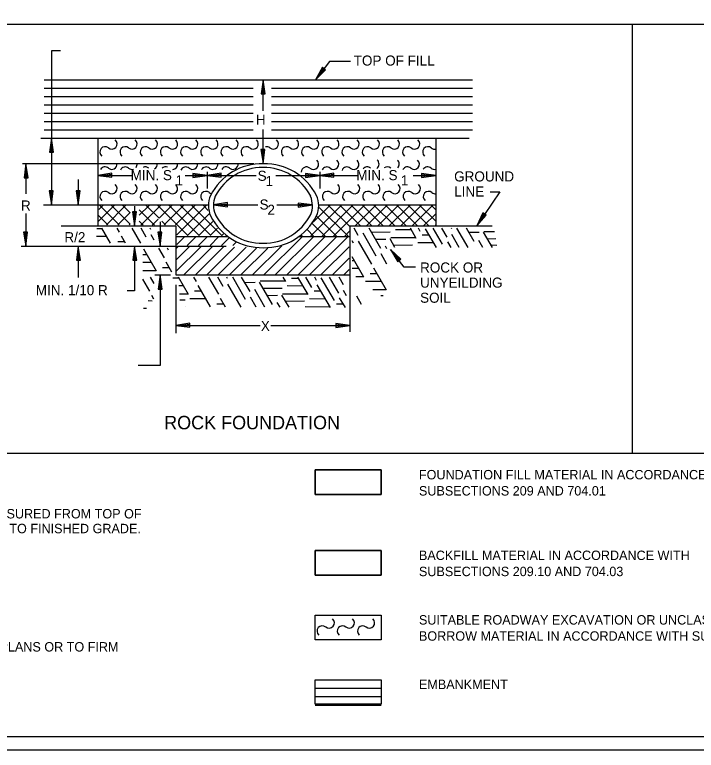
# Model space of a CAD drawing. Extents: x 0 to 390, y 0 to 265.
# Drawn here: x 144.9 to 271.5, y 0 to 136.7 of the extents above; entities that cross this region are included whole.
import ezdxf

# ---------------------------------------------------------------- set-up
doc = ezdxf.new("R2010")
doc.units = 0
doc.layers.add('D_Details', color=7, linetype='Continuous')
doc.layers.add('Default', color=7, linetype='Continuous')

msp = doc.modelspace()

# ---------------------------------------------------------------- linework, layer by layer
at = {"layer": 'D_Details'}
for p, q in [((-0.22, 135.01), (388.66, 135.01)), ((259.59, 135.01), (259.59, 55.26)), ((153.41, 130), (151.71, 130)), ((151.71, 130), (151.71, 113.8)), ((203.41, 128.05), (200.79, 124.64)), ((207.3, 128.05), (203.41, 128.05)), ((202.06, 126.97), (200.79, 124.64)), ((200.79, 124.64), (202.66, 126.51)), ((201.19, 125.16), (202.21, 126.86)), ((202.51, 126.63), (201.19, 125.16)), ((201.8, 125.99), (202.29, 126.8)), ((202.43, 126.69), (201.8, 125.99)), ((202.66, 126.51), (202.06, 126.97)), ((150.37, 124.64), (229.93, 124.64)), ((191.05, 124.64), (190.71, 122.01)), ((191.46, 122.01), (191.05, 124.64)), ((191.05, 118.85), (191.05, 124.64)), ((150.37, 123.09), (189.18, 123.09)), ((190.9, 122.01), (191.05, 123.98)), ((191.05, 123.98), (191.28, 122.01)), ((192.62, 123.09), (229.93, 123.09)), ((190.71, 122.01), (191.46, 122.01)), ((191, 122.01), (191.07, 122.95)), ((191.07, 122.95), (191.18, 122.01)), ((150.37, 121.54), (189.18, 121.54)), ((192.62, 121.54), (229.93, 121.54)), ((150.37, 119.99), (189.18, 119.99)), ((192.62, 119.99), (229.93, 119.99)), ((150.37, 118.45), (189.18, 118.45)), ((192.62, 118.45), (229.93, 118.45)), ((150.37, 116.9), (189.18, 116.9)), ((192.62, 116.9), (229.93, 116.9)), ((150.37, 115.35), (189.18, 115.35)), ((191.05, 109.05), (191.05, 115.38)), ((192.62, 115.35), (229.93, 115.35)), ((149.76, 113.8), (229.32, 113.8)), ((151.71, 113.8), (151.37, 111.18)), ((151.71, 113.8), (151.71, 101.39)), ((152.12, 111.18), (151.71, 113.8)), ((160.35, 113.8), (160.35, 97.49)), ((223.12, 113.8), (223.12, 97.49)), ((151.56, 111.18), (151.71, 113.15)), ((151.71, 113.15), (151.93, 111.18)), ((151.37, 111.18), (152.12, 111.18)), ((151.65, 111.18), (151.73, 112.12)), ((151.73, 112.12), (151.84, 111.18)), ((191.39, 111.67), (190.64, 111.67)), ((190.64, 111.67), (191.05, 109.05)), ((191.05, 109.71), (190.83, 111.67)), ((191.03, 110.74), (190.92, 111.67)), ((191.11, 111.67), (191.03, 110.74)), ((191.05, 109.05), (191.39, 111.67)), ((191.2, 111.67), (191.05, 109.71)), ((146.36, 109.06), (189.34, 109.06)), ((146.97, 109.06), (146.63, 106.43)), ((146.82, 106.43), (146.97, 108.4)), ((147.38, 106.43), (146.97, 109.06)), ((146.97, 109.06), (146.97, 103.41)), ((146.97, 108.4), (147.19, 106.43)), ((146.91, 106.43), (146.98, 107.37)), ((146.98, 107.37), (147.1, 106.43)), ((162.97, 107.28), (160.35, 106.86)), ((160.35, 106.86), (162.97, 106.53)), ((160.35, 106.86), (166.66, 106.86)), ((161, 106.86), (162.97, 107.09)), ((162.97, 106.71), (161, 106.86)), ((162.03, 106.88), (162.97, 107)), ((162.97, 106.81), (162.03, 106.88)), ((162.97, 106.53), (162.97, 107.28)), ((176.55, 106.86), (180.64, 106.86)), ((180.64, 106.86), (178.02, 107.2)), ((178.02, 107.2), (178.02, 106.45)), ((178.02, 107.01), (179.99, 106.86)), ((178.02, 106.92), (178.96, 106.85)), ((178.02, 106.45), (180.64, 106.86)), ((179.99, 106.86), (178.02, 106.64)), ((178.96, 106.85), (178.02, 106.73)), ((180.64, 107.55), (180.64, 104.43)), ((183.27, 107.28), (180.64, 106.86)), ((180.64, 106.86), (183.27, 106.53)), ((180.64, 106.86), (189.74, 106.86)), ((181.3, 106.86), (183.27, 107.09)), ((183.27, 106.71), (181.3, 106.86)), ((182.33, 106.88), (183.27, 107)), ((183.27, 106.81), (182.33, 106.88)), ((183.27, 106.53), (183.27, 107.28)), ((193.42, 106.86), (201.57, 106.86)), ((201.57, 106.86), (198.94, 107.2)), ((198.94, 107.2), (198.94, 106.45)), ((198.94, 107.01), (200.91, 106.86)), ((198.94, 106.92), (199.88, 106.85)), ((198.94, 106.45), (201.57, 106.86)), ((200.91, 106.86), (198.94, 106.64)), ((199.88, 106.85), (198.94, 106.73)), ((201.57, 107.55), (201.57, 104.43)), ((204.19, 107.28), (201.57, 106.86)), ((201.57, 106.86), (204.19, 106.53)), ((201.57, 106.86), (208.53, 106.86)), ((202.22, 106.86), (204.19, 107.09)), ((204.19, 106.71), (202.22, 106.86)), ((203.25, 106.88), (204.19, 107)), ((204.19, 106.81), (203.25, 106.88)), ((204.19, 106.53), (204.19, 107.28)), ((218.92, 106.86), (223.12, 106.86)), ((223.12, 106.86), (220.49, 107.2)), ((220.49, 107.2), (220.49, 106.45)), ((220.49, 107.01), (222.46, 106.86)), ((220.49, 106.92), (221.43, 106.85)), ((220.49, 106.45), (223.12, 106.86)), ((222.46, 106.86), (220.49, 106.64)), ((221.43, 106.85), (220.49, 106.73)), ((146.63, 106.43), (147.38, 106.43)), ((156.7, 106.13), (156.7, 101.39)), ((152.05, 104.01), (151.3, 104.01)), ((151.3, 104.01), (151.71, 101.39)), ((151.71, 102.04), (151.48, 104.01)), ((151.69, 103.07), (151.58, 104.01)), ((151.77, 104.01), (151.69, 103.07)), ((151.71, 101.39), (152.05, 104.01)), ((151.86, 104.01), (151.71, 102.04)), ((157.03, 104.01), (156.29, 104.01)), ((156.29, 104.01), (156.7, 101.39)), ((156.7, 102.04), (156.47, 104.01)), ((156.68, 103.07), (156.57, 104.01)), ((156.75, 104.01), (156.68, 103.07)), ((156.7, 101.39), (157.03, 104.01)), ((156.85, 104.01), (156.7, 102.04)), ((235.04, 103.82), (230.74, 97.49)), ((233.21, 103.82), (235.04, 103.82)), ((150.25, 101.39), (180.9, 101.39)), ((160.47, 98.36), (163.38, 101.27)), ((160.51, 100.52), (161.26, 101.27)), ((164.31, 97.69), (160.73, 101.27)), ((161.92, 97.69), (165.51, 101.27)), ((166.33, 97.79), (162.85, 101.27)), ((166.33, 99.92), (164.97, 101.27)), ((168.05, 99.46), (169.87, 101.27)), ((168.34, 97.63), (171.99, 101.27)), ((171.71, 98.91), (169.35, 101.27)), ((177.04, 95.7), (171.47, 101.27)), ((171.74, 98.91), (174.11, 101.27)), ((172.65, 97.69), (176.23, 101.27)), ((179.18, 95.69), (173.59, 101.27)), ((174.77, 97.69), (178.35, 101.27)), ((175.03, 95.83), (180.47, 101.27)), ((181.31, 95.67), (175.71, 101.27)), ((183.45, 95.66), (177.83, 101.27)), ((180.86, 100.37), (179.95, 101.27)), ((184.42, 101.8), (181.8, 101.39)), ((181.8, 101.39), (184.42, 101.05)), ((181.8, 101.39), (190.06, 101.39)), ((182.46, 101.39), (184.42, 101.61)), ((184.42, 101.24), (182.46, 101.39)), ((183.49, 101.4), (184.42, 101.52)), ((184.42, 101.33), (183.49, 101.4)), ((184.42, 101.05), (184.42, 101.8)), ((193.59, 101.39), (200.21, 101.39)), ((200.21, 101.39), (197.59, 101.72)), ((197.59, 101.72), (197.59, 100.97)), ((197.59, 101.54), (199.56, 101.39)), ((197.59, 101.44), (198.53, 101.37)), ((197.59, 100.97), (200.21, 101.39)), ((199.56, 101.39), (197.59, 101.16)), ((198.53, 101.37), (197.59, 101.25)), ((205.62, 101.34), (199.89, 95.61)), ((203.5, 101.34), (200.34, 98.18)), ((201.39, 101.39), (223.12, 101.39)), ((207.74, 101.34), (202, 95.59)), ((206.95, 97.55), (203.16, 101.34)), ((209.86, 101.34), (204.1, 95.58)), ((209.08, 97.55), (205.28, 101.34)), ((211.2, 97.55), (207.4, 101.34)), ((211.99, 101.34), (208.19, 97.55)), ((213.32, 97.55), (209.52, 101.34)), ((214.11, 101.34), (210.31, 97.55)), ((215.44, 97.55), (211.64, 101.34)), ((216.23, 101.34), (212.43, 97.55)), ((217.56, 97.55), (213.76, 101.34)), ((218.35, 101.34), (214.55, 97.55)), ((219.68, 97.55), (215.88, 101.34)), ((220.47, 101.34), (216.67, 97.55)), ((221.8, 97.55), (218.01, 101.34)), ((222.59, 101.34), (218.79, 97.55)), ((223.05, 98.41), (220.13, 101.34)), ((223.05, 100.53), (222.25, 101.34)), ((164.04, 97.69), (166.33, 99.97)), ((167.5, 100.11), (166.75, 100.11)), ((166.75, 100.11), (167.16, 97.49)), ((167.16, 98.15), (166.93, 100.11)), ((167.14, 99.18), (167.03, 100.11)), ((167.22, 100.11), (167.14, 99.18)), ((167.16, 101.17), (167.16, 97.49)), ((167.16, 97.49), (167.5, 100.11)), ((167.31, 100.11), (167.16, 98.15)), ((170.87, 97.63), (168.05, 100.45)), ((206.82, 95.56), (201.46, 100.92)), ((231.87, 99.89), (230.74, 97.49)), ((232.49, 99.47), (231.87, 99.89)), ((146.97, 99.81), (146.97, 93.72)), ((162.19, 97.69), (160.49, 99.39)), ((170.46, 97.63), (171.58, 98.75)), ((177.02, 95.7), (181.02, 99.7)), ((204.68, 95.58), (201.02, 99.24)), ((223.05, 99.68), (220.92, 97.55)), ((230.74, 97.49), (232.49, 99.47)), ((231.11, 98.03), (232.03, 99.79)), ((232.34, 99.58), (231.11, 98.03)), ((231.67, 98.9), (232.1, 99.73)), ((232.26, 99.63), (231.67, 98.9)), ((153.53, 97.49), (174.82, 97.49)), ((166.16, 97.69), (166.33, 97.85)), ((168.75, 97.63), (168.05, 98.33)), ((171.9, 98.22), (171.9, 93.72)), ((172.93, 97.69), (172.25, 98.37)), ((174.82, 97.49), (174.82, 88.36)), ((179.12, 95.69), (181.73, 98.29)), ((202.55, 95.59), (200.19, 97.95)), ((207.09, 97.41), (206.97, 97.53)), ((207.18, 97.49), (207.18, 77.77)), ((207.18, 97.49), (233.58, 97.49)), ((223.05, 97.56), (223.04, 97.55)), ((147.3, 96.34), (146.55, 96.34)), ((146.55, 96.34), (146.97, 93.72)), ((146.97, 94.37), (146.74, 96.34)), ((146.95, 95.4), (146.83, 96.34)), ((147.02, 96.34), (146.95, 95.4)), ((146.97, 93.72), (147.3, 96.34)), ((147.12, 96.34), (146.97, 94.37)), ((161.16, 96.91), (160.18, 96.92)), ((162.67, 94.27), (161.08, 97.03)), ((164.37, 96.33), (163.96, 97.03)), ((168.33, 94.27), (166.74, 97.03)), ((169.33, 95.37), (168.38, 97.03)), ((170.17, 96.83), (170.05, 97.03)), ((170.8, 94.82), (170.24, 95.8)), ((172.24, 96.34), (171.49, 96.34)), ((171.49, 96.34), (171.9, 93.72)), ((171.9, 94.37), (171.68, 96.34)), ((171.88, 95.4), (171.77, 96.34)), ((171.96, 96.34), (171.88, 95.4)), ((171.9, 93.72), (172.24, 96.34)), ((172.05, 96.34), (171.9, 94.37)), ((181.23, 95.67), (182.59, 97.03)), ((183.34, 95.66), (183.71, 96.03)), ((198.28, 95.62), (198.12, 95.78)), ((200.41, 95.6), (199.28, 96.74)), ((207.12, 96.47), (206.21, 95.57)), ((208.72, 95.7), (207.95, 97.03)), ((212.04, 91.84), (209.61, 96.1)), ((212.89, 93.3), (210.73, 97.03)), ((214.66, 96.3), (211.21, 96.25)), ((218.51, 96.72), (215.62, 96.74)), ((219.51, 95.15), (218.4, 97.03)), ((220.22, 96.46), (219.89, 97.03)), ((221.91, 95.75), (220.61, 95.76)), ((223.24, 93.48), (221.2, 96.94)), ((224.39, 94.06), (222.67, 97.03)), ((225.24, 95.38), (224.28, 97.03)), ((226.11, 96.96), (226.07, 97.03)), ((227.5, 93.48), (226.11, 95.88)), ((229.12, 93.48), (227.05, 97.03)), ((230.28, 94.56), (228.83, 97.03)), ((231.17, 96.25), (229.32, 96.28)), ((233.67, 93.48), (232.01, 96.33)), ((234.02, 96.36), (232.08, 96.37)), ((161.89, 95.49), (160.11, 95.5)), ((165.32, 94.51), (164.03, 94.52)), ((165.45, 94.27), (164.71, 95.55)), ((174.82, 95.54), (184.47, 95.54)), ((175, 94.01), (176.43, 95.44)), ((176.94, 93.83), (178.54, 95.44)), ((179.06, 93.83), (180.66, 95.43)), ((181.18, 93.83), (182.78, 95.43)), ((183.31, 93.83), (184.68, 95.21)), ((185.43, 93.83), (186.04, 94.45)), ((191.25, 88.42), (198.23, 95.4)), ((193.37, 88.42), (200.35, 95.4)), ((195.49, 88.42), (202.47, 95.4)), ((197.61, 88.42), (204.59, 95.4)), ((197.75, 95.54), (207.18, 95.54)), ((199.73, 88.42), (206.71, 95.4)), ((207.87, 94.24), (207.61, 94.7)), ((211.25, 90.39), (208.79, 94.67)), ((213.84, 94.95), (212.01, 94.93)), ((215.55, 93.48), (214.65, 95.05)), ((219.43, 95.24), (214.76, 95.25)), ((225.99, 93.48), (225.37, 94.53)), ((231.88, 93.48), (231.14, 94.75)), ((234.26, 95.05), (232.74, 95.04)), ((146.11, 93.72), (184.19, 93.72)), ((156.7, 93.72), (156.36, 91.09)), ((156.55, 91.09), (156.7, 93.06)), ((156.7, 93.72), (156.7, 87.87)), ((157.11, 91.09), (156.7, 93.72)), ((156.7, 93.06), (156.92, 91.09)), ((167.16, 93.72), (166.82, 91.09)), ((167.01, 91.09), (167.16, 93.06)), ((167.16, 93.72), (167.16, 85.44)), ((167.57, 91.09), (167.16, 93.72)), ((167.16, 93.06), (167.38, 91.09)), ((171.24, 89.06), (168.88, 93.14)), ((172.7, 91.52), (171.65, 93.35)), ((173.49, 92.96), (173.27, 93.35)), ((174.92, 93.3), (175.25, 93.64)), ((174.92, 91.18), (177.36, 93.62)), ((174.92, 89.06), (179.46, 93.6)), ((176.4, 88.42), (181.56, 93.58)), ((178.52, 88.42), (183.66, 93.56)), ((180.64, 88.42), (185.76, 93.54)), ((182.76, 88.42), (187.87, 93.52)), ((184.88, 88.42), (189.79, 93.33)), ((187, 88.42), (191.9, 93.31)), ((189.13, 88.42), (194.5, 93.79)), ((201.85, 88.42), (207.04, 93.61)), ((214.05, 93.21), (213.78, 93.69)), ((217.28, 89.82), (214.72, 93.11)), ((214.72, 93.11), (216.07, 90.83)), ((216.66, 91.29), (214.72, 93.11)), ((218.83, 93.89), (215.38, 93.85)), ((222.68, 94.31), (219.79, 94.33)), ((234.48, 93.86), (233.49, 93.87)), ((156.64, 91.09), (156.72, 92.03)), ((156.72, 92.03), (156.83, 91.09)), ((167.1, 91.09), (167.18, 92.03)), ((167.18, 92.03), (167.29, 91.09)), ((169.49, 92.1), (168.72, 92.11)), ((209.79, 87.93), (207.61, 91.7)), ((214.05, 90.35), (212.95, 92.26)), ((216.22, 90.94), (215.13, 92.59)), ((215.13, 92.59), (216.51, 91.17)), ((216.29, 91), (215.77, 91.79)), ((215.77, 91.79), (216.44, 91.12)), ((156.36, 91.09), (157.11, 91.09)), ((166.82, 91.09), (167.57, 91.09)), ((170.23, 90.68), (168.72, 90.69)), ((174.11, 88.89), (173.05, 90.74)), ((203.97, 88.42), (207.04, 91.48)), ((208.04, 90.98), (207.61, 90.98)), ((216.07, 90.83), (216.66, 91.29)), ((171.19, 89.13), (168.72, 89.15)), ((173.66, 89.69), (172.36, 89.7)), ((206.09, 88.42), (207.04, 89.36)), ((208.77, 89.55), (207.61, 89.56)), ((213.95, 85.53), (211.59, 89.61)), ((219.35, 89.82), (217.28, 89.82)), ((170.01, 85.33), (168.72, 87.56)), ((170.8, 86.78), (170.12, 87.96)), ((170.93, 88.36), (173.83, 88.36)), ((171.9, 88.36), (171.57, 85.74)), ((171.75, 85.74), (171.9, 87.7)), ((171.9, 88.36), (171.9, 71.56)), ((172.32, 85.74), (171.9, 88.36)), ((171.9, 87.7), (172.13, 85.74)), ((175.44, 87.76), (174.3, 87.77)), ((174.82, 88.36), (207.18, 88.36)), ((177.19, 84.71), (175.32, 87.96)), ((178.65, 87.17), (178.2, 87.96)), ((182.82, 84.77), (180.98, 87.96)), ((183.61, 86.21), (182.61, 87.96)), ((184.45, 87.68), (184.29, 87.96)), ((187.78, 83.81), (185.41, 87.96)), ((188.62, 85.27), (187.06, 87.96)), ((195.24, 87.12), (194.75, 87.96)), ((197.64, 87.72), (196.35, 87.73)), ((199.41, 84.71), (197.5, 87.96)), ((200.13, 86.03), (199.01, 87.96)), ((200.98, 87.36), (200.63, 87.96)), ((204.29, 83.62), (201.84, 87.85)), ((205.14, 84.95), (203.39, 87.96)), ((206.01, 86.53), (205.18, 87.96)), ((209.74, 88), (208.3, 88.01)), ((212.2, 88.57), (210.91, 88.58)), ((171.85, 85.74), (171.92, 86.67)), ((171.92, 86.67), (172.03, 85.74)), ((174.82, 86.54), (174.82, 77.52)), ((176.18, 86.34), (175.36, 86.34)), ((181.29, 82.41), (179, 86.4)), ((186.97, 82.39), (184.52, 86.64)), ((189.58, 86.93), (187.74, 86.9)), ((192.79, 82.86), (190.38, 87.02)), ((195.16, 87.21), (190.49, 87.22)), ((198.41, 86.28), (195.52, 86.31)), ((203.57, 82.32), (201.11, 86.5)), ((212.94, 87.15), (210.05, 87.17)), ((167.16, 85.44), (165.82, 85.44)), ((171.57, 85.74), (172.32, 85.74)), ((177.14, 84.78), (175.49, 84.8)), ((179.6, 85.35), (178.31, 85.36)), ((191.39, 82.37), (189.51, 85.66)), ((194.56, 85.87), (191.12, 85.82)), ((199.33, 84.8), (194.66, 84.81)), ((201.81, 85.32), (200.51, 85.33)), ((206.56, 84.49), (206.01, 85.45)), ((213.91, 85.6), (211.44, 85.62)), ((170.44, 83.51), (169.67, 83.52)), ((170.73, 83.89), (170.35, 84.55)), ((176.59, 83.67), (175.58, 83.67)), ((180.34, 83.93), (177.45, 83.95)), ((184.08, 82.4), (183.16, 83.99)), ((189.76, 82.38), (188.69, 84.24)), ((193.74, 84.52), (191.91, 84.5)), ((195.86, 82.35), (194.55, 84.62)), ((198.73, 83.46), (195.28, 83.41)), ((202.58, 83.88), (199.69, 83.9)), ((206.33, 82.31), (205.27, 84.1)), ((209.34, 82.86), (208.44, 84.41)), ((213.35, 84.49), (212.92, 84.48)), ((169.37, 82.11), (168.81, 82.11)), ((176.63, 82.43), (176.62, 82.44)), ((183.77, 82.95), (182.48, 82.96)), ((194.19, 82.36), (193.68, 83.26)), ((203.5, 82.4), (198.83, 82.41)), ((205.97, 82.91), (204.68, 82.92)), ((177.45, 79.4), (174.82, 78.98)), ((177.45, 78.65), (177.45, 79.4)), ((207.18, 78.98), (204.56, 79.32)), ((204.56, 79.32), (204.56, 78.57)), ((174.82, 78.98), (177.45, 78.65)), ((174.82, 78.98), (190.52, 78.98)), ((175.48, 78.98), (177.45, 79.21)), ((177.45, 78.83), (175.48, 78.98)), ((176.51, 79), (177.45, 79.12)), ((177.45, 78.93), (176.51, 79)), ((192.46, 78.98), (207.18, 78.98)), ((204.56, 79.13), (206.53, 78.98)), ((204.56, 79.04), (205.49, 78.97)), ((204.56, 78.57), (207.18, 78.98)), ((206.53, 78.98), (204.56, 78.76)), ((205.49, 78.97), (204.56, 78.85)), ((171.9, 71.56), (167.84, 71.56)), ((-0.22, 55.26), (389.68, 55.26)), ((200.72, 13.12), (212.99, 13.12)), ((200.72, 11.55), (212.99, 11.55)), ((200.72, 9.97), (212.99, 9.97)), ((200.72, 8.4), (212.99, 8.4))]:
    msp.add_line(p, q, dxfattribs=at)
for points in [[(200.72, 52.11), (212.99, 52.11), (212.99, 47.55), (200.72, 47.55)], [(212.99, 47.55), (212.99, 52.11), (200.72, 52.11), (200.72, 47.55)], [(200.72, 37.12), (212.99, 37.12), (212.99, 32.56), (200.72, 32.56)], [(200.72, 32.56), (212.99, 32.56), (212.99, 37.12), (200.72, 37.12)], [(200.72, 25.12), (212.99, 25.12), (212.99, 20.56), (200.72, 20.56)], [(200.72, 13.12), (212.99, 13.12), (212.99, 8.56), (200.72, 8.56)]]:
    msp.add_lwpolyline(points, close=True, dxfattribs=at)
for centre, radius, start, end in [((161.68, 111.22), 0.975, 50, 230), ((162.93, 112.71), 0.975, 230, 50), ((165.43, 111.22), 0.975, 50, 230), ((166.68, 112.71), 0.975, 230, 50), ((169.18, 111.22), 0.975, 50, 230), ((170.43, 112.71), 0.975, 230, 50), ((172.93, 111.22), 0.975, 50, 230), ((174.18, 112.71), 0.975, 230, 50), ((176.68, 111.22), 0.975, 50, 230), ((177.93, 112.71), 0.975, 230, 50), ((180.43, 111.22), 0.975, 50, 230), ((181.68, 112.71), 0.975, 230, 50), ((184.18, 111.22), 0.975, 50, 230), ((185.43, 112.71), 0.975, 230, 50), ((187.92, 111.22), 0.975, 50, 230), ((189.18, 112.71), 0.975, 230, 50), ((191.67, 111.22), 0.975, 50, 100.3519), ((192.93, 112.71), 0.975, 230, 50), ((195.42, 111.22), 0.975, 50, 230), ((196.68, 112.71), 0.975, 230, 50), ((199.17, 111.22), 0.975, 50, 230), ((200.43, 112.71), 0.975, 230, 50), ((202.92, 111.22), 0.975, 50, 230), ((204.17, 112.71), 0.975, 230, 50), ((206.67, 111.22), 0.975, 50, 230), ((207.92, 112.71), 0.975, 230, 50), ((210.42, 111.22), 0.975, 50, 230), ((211.67, 112.71), 0.975, 230, 50), ((214.17, 111.22), 0.975, 50, 230), ((215.42, 112.71), 0.975, 230, 50), ((217.92, 111.22), 0.975, 50, 230), ((219.17, 112.71), 0.975, 230, 50), ((221.67, 111.22), 0.975, 50, 230), ((222.92, 112.71), 0.975, 230, 281.7049), ((200.38, 108.96), 0.975, 230, 50), ((204.13, 108.96), 0.975, 230, 50), ((207.87, 108.96), 0.975, 230, 50), ((211.62, 108.96), 0.975, 306.4815, 50), ((215.37, 108.96), 0.975, 316.6627, 50), ((219.12, 108.96), 0.975, 230, 50), ((161.68, 107.47), 0.975, 50, 150.0188), ((162.93, 108.96), 0.975, 230, 5.3689), ((165.43, 107.47), 0.975, 50, 156.2177), ((166.68, 108.96), 0.975, 230, 287.1005), ((166.68, 108.96), 0.975, 321.2721, 5.3689), ((169.18, 107.47), 0.975, 50, 116.9826), ((170.43, 108.96), 0.975, 297.7848, 5.3689), ((172.93, 107.47), 0.975, 68.4584, 131.518), ((174.18, 108.96), 0.975, 276.8204, 5.3689), ((176.68, 107.47), 0.975, 50, 158.314), ((177.93, 108.96), 0.975, 230, 5.3689), ((180.43, 107.47), 0.975, 50, 150.9949), ((181.68, 108.96), 0.975, 230, 5.3689), ((190.92, 98.2), 10.85, 89.0105, 152.9614), ((190.86, 98.56), 9.77, 89.0105, 152.9614), ((184.18, 107.47), 0.975, 50, 148.0224), ((185.43, 108.96), 0.975, 230, 5.3689), ((191.19, 98.56), 9.77, 27.0239, 90.9895), ((191.3, 98.2), 10.85, 27.0239, 90.9895), ((199.12, 107.47), 0.975, 50, 179.7517), ((202.87, 107.47), 0.975, 50, 153.5798), ((206.62, 107.47), 0.975, 50, 159.9587), ((210.37, 107.47), 0.975, 50, 140.0137), ((214.12, 107.47), 0.975, 50, 126.2228), ((217.87, 107.47), 0.975, 50, 148.9806), ((221.62, 107.47), 0.975, 50, 147.1532), ((222.87, 108.96), 0.975, 230, 284.6447), ((162.93, 104.43), 0.975, 230, 50), ((166.68, 104.43), 0.975, 230, 50), ((170.43, 104.43), 0.975, 230, 50), ((174.18, 104.43), 0.975, 230, 50), ((177.93, 104.43), 0.975, 230, 50), ((204.29, 104.43), 0.975, 230, 50), ((208.04, 104.43), 0.975, 230, 50), ((211.79, 104.43), 0.975, 230, 50), ((215.54, 104.43), 0.975, 230, 50), ((219.29, 104.43), 0.975, 230, 50), ((161.68, 102.93), 0.975, 50, 230), ((165.43, 102.93), 0.975, 50, 230), ((169.18, 102.93), 0.975, 50, 230), ((172.93, 102.93), 0.975, 50, 230), ((176.68, 102.93), 0.975, 50, 230), ((180.43, 102.93), 0.975, 50, 230), ((186.01, 101.25), 5.11, 158.4108, 201.9935), ((181.68, 104.43), 0.975, 230, 250.6002), ((185.74, 101.37), 3.94, 155.4973, 206.4604), ((195.7, 101.25), 4.51, 338.3003, 22.6129), ((196.88, 101.25), 4.51, 334.8709, 24.6806), ((203.04, 102.93), 0.975, 50, 230), ((206.79, 102.93), 0.975, 50, 230), ((210.53, 102.93), 0.975, 50, 230), ((214.28, 102.93), 0.975, 50, 230), ((218.03, 102.93), 0.975, 50, 230), ((221.78, 102.93), 0.975, 50, 230), ((223.03, 104.43), 0.975, 230, 274.8531), ((190.92, 104.27), 10.85, 207.0386, 270.9895), ((190.86, 104.02), 9.77, 207.0386, 270.9895), ((191.19, 104.02), 9.77, 269.0105, 332.9761), ((191.3, 104.27), 10.85, 269.0105, 332.9761), ((203.31, 23.67), 0.975, 230, 50), ((207.05, 23.67), 0.975, 230, 50), ((210.8, 23.67), 0.975, 230, 50), ((202.05, 22.17), 0.975, 50, 230), ((205.8, 22.17), 0.975, 50, 230), ((209.55, 22.17), 0.975, 50, 230)]:
    msp.add_arc(centre, radius, start, end, dxfattribs=at)
at = {"layer": 'Default'}
for points in [[(0, 265), (326.25, 265), (326.25, 255), (390, 255), (390, 37.5), (315, 37.5), (315, 0), (0, 0)], [(0, 262.5), (326.25, 262.5), (326.25, 252.5), (390, 252.5), (390, 40), (315, 40), (315, 2.5), (0, 2.5)]]:
    msp.add_lwpolyline(points, close=True, dxfattribs=at)

# ---------------------------------------------------------------- texts
at = {"layer": 'D_Details'}
for s, height, p in [('TOP OF FILL', 1.8745, (207.88, 127.28)), ('H', 1.87, (189.7, 116.3)), ('MIN. S', 1.875, (166.44, 105.98)), ('1', 1.87, (174.78, 105.01)), ('S', 1.87, (190.03, 105.86)), ('1', 1.87, (191.49, 104.89)), ('MIN. S', 1.875, (208.36, 105.98)), ('1', 1.87, (216.63, 105.01)), ('GROUND', 1.875, (226.54, 105.74)), ('LINE', 1.875, (226.54, 102.93)), ('R', 1.87, (146.06, 100.34)), ('S', 1.87, (190.39, 100.52)), ('2', 1.87, (191.85, 99.54)), ('R/2', 1.875, (154.13, 94.44)), ('ROCK OR', 1.875, (220.21, 88.81)), ('UNYEILDING', 1.875, (220.21, 86)), ('MIN. 1/10 R', 1.8745, (148.81, 84.6)), ('SOIL', 1.875, (220.21, 83.19)), ('X', 1.87, (190.63, 77.94)), ('ROCK FOUNDATION', 2.4994, (172.66, 59.67)), ('FOUNDATION FILL MATERIAL IN ACCORDANCE WITH', 1.7496, (220, 50.36)), ('SUBSECTIONS 209 AND 704.01', 1.7496, (220, 47.36)), ('HEIGHT OF COVER MEASURED FROM TOP OF', 1.7496, (115.95, 43.1)), ('DRAINAGE STRUCTURE TO FINISHED GRADE.', 1.7496, (115.95, 40.35)), ('BACKFILL MATERIAL IN ACCORDANCE WITH', 1.7496, (220, 35.37)), ('SUBSECTIONS 209.10 AND 704.03', 1.7496, (220, 32.37)), ('SUITABLE ROADWAY EXCAVATION OR UNCLASSIFIED', 1.7496, (220, 23.37)), ('BORROW MATERIAL IN ACCORDANCE WITH SUBSECTION 209.10', 1.7496, (220, 20.37)), ('DEPTH AS SHOWN ON PLANS OR TO FIRM', 1.7496, (115.95, 18.36)), ('EMBANKMENT', 1.75, (220, 11.37))]:
    msp.add_text(s, height=height, dxfattribs=at).set_placement(p)

doc.saveas('drawing.dxf')
